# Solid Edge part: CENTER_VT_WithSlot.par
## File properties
Author: haileyy
Template: ansi part.par
Last saved by: haileyy
Revision: 1
Application: Solid Edge
Accuracy: 0.990
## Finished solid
Body 1: solid body, 72 faces, 209 edges, 138 vertices.
  Faces by surface: plane 48, swept 14, cylinder 10
  Edges by curve: line 161, spline 28, circle 20
Bounding box of the edges (mm; curved faces can reach further): 304.516 x 36.610 x 3.175, from (-131.5411, 92.0409, -3.175) to (172.9749, 128.6504, 0).
Cylindrical faces by radius (mm): R6.985 x1, R10.898 x1, R10.9558 x1, R14.7923 x1, R18.4738 x1, R22.3884 x1, R176.8404 x1, R335.9417 x1, R1198.6716 x1, R1298.465 x1
Planar faces by outward normal: +x 7, +y 5, +z 1, -x 7, -y 6, -z 1, oblique 21
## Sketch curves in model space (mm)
spline (131.9767, 104.6649, 0) -> (135.9126, 105.1396, 0) -> (139.8482, 105.6168, 0)
line (-125.3481, 108.7055, 0) -> (-131.5411, 108.6981, 0)
spline (-131.5411, 108.6981, 0) -> (-123.0323, 101.8557, 0) -> (-112.4426, 98.3032, 0)
spline (-123.1479, 101.8858, 0) -> (-117.6944, 99.8247, 0) -> (-113.2993, 98.5347, 0)
spline (-131.2858, 108.1006, 0) -> (-127.7105, 104.3642, 0) -> (-123.1479, 101.8858, 0)
spline (139.7517, 114.3087, 0) -> (156.3369, 112.4673, 0) -> (172.9749, 111.1502, 0)
spline (139.7517, 114.3087, 0) -> (156.3386, 112.4674, 0) -> (172.9749, 111.1502, 0)
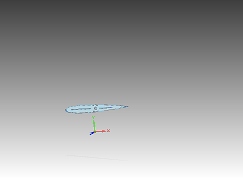
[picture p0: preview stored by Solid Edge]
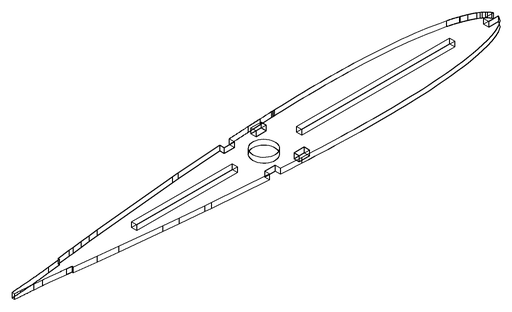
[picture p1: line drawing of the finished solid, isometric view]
